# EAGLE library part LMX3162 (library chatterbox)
Single Chip Radio Transceiver
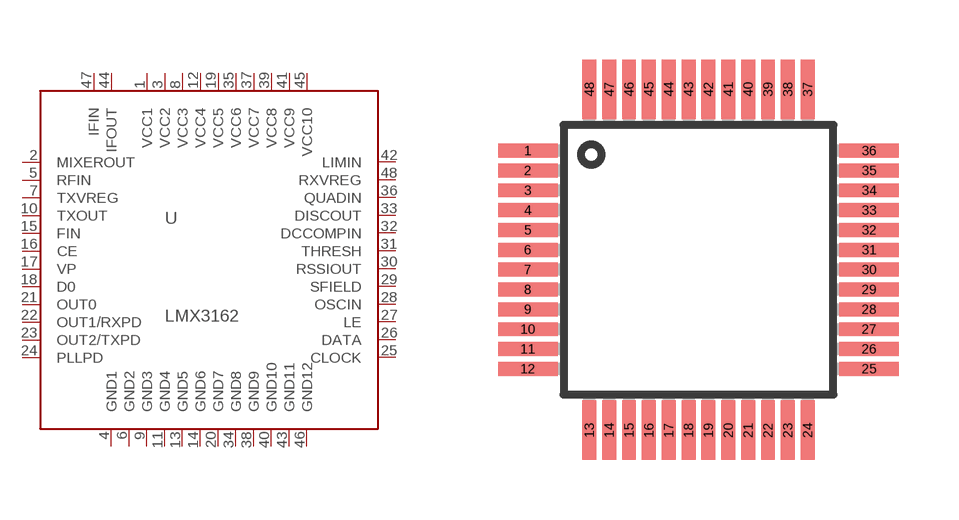
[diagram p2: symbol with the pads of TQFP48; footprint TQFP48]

Designator prefix -

## LMX3162VBH  [TQFP48]
1  VCC1  pas
2  MIXEROUT  pas
3  VCC2  pas
4  GND1  pas
5  RFIN  pas
6  GND2  pas
7  TXVREG  pas
8  VCC3  pas
9  GND3  pas
10  TXOUT  pas
11  GND4  pas
12  VCC4  pas
13  GND5
14  GND6
15  FIN
16  CE
17  VP
18  D0
19  VCC5
20  GND7
21  OUT0
22  OUT1/RXPD
23  OUT2/TXPD
24  PLLPD
25  CLOCK
26  DATA
27  LE
28  OSCIN  in
29  SFIELD  in
30  RSSIOUT  in
31  THRESH  in
32  DCCOMPIN  out
33  DISCOUT
34  GND8
35  VCC6
36  QUADIN
37  VCC7
38  GND9
39  VCC8
40  GND10
41  VCC9
42  LIMIN
43  GND11
44  IFOUT
45  VCC10
46  GND12
47  IFIN
48  RXVREG

## Footprint TQFP48 (pad centres in mm)
smd 1.5 x 0.35: 1 -4.3,2.75; 2 -4.3,2.25; 3 -4.3,1.75; 4 -4.3,1.25; 5 -4.3,0.75; 6 -4.3,0.25; 7 -4.3,-0.25; 8 -4.3,-0.75; 9 -4.3,-1.25; 10 -4.3,-1.75; 11 -4.3,-2.25; 12 -4.3,-2.75; 25 4.3,-2.75; 26 4.3,-2.25; 27 4.3,-1.75; 28 4.3,-1.25; 29 4.3,-0.75; 30 4.3,-0.25; 31 4.3,0.25; 32 4.3,0.75; 33 4.3,1.25; 34 4.3,1.75; 35 4.3,2.25; 36 4.3,2.75
smd 0.35 x 1.5: 13 -2.75,-4.3; 14 -2.25,-4.3; 15 -1.75,-4.3; 16 -1.25,-4.3; 17 -0.75,-4.3; 18 -0.25,-4.3; 19 0.25,-4.3; 20 0.75,-4.3; 21 1.25,-4.3; 22 1.75,-4.3; 23 2.25,-4.3; 24 2.75,-4.3; 37 2.75,4.3; 38 2.25,4.3; 39 1.75,4.3; 40 1.25,4.3; 41 0.75,4.3; 42 0.25,4.3; 43 -0.25,4.3; 44 -0.75,4.3; 45 -1.25,4.3; 46 -1.75,4.3; 47 -2.25,4.3; 48 -2.75,4.3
